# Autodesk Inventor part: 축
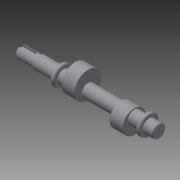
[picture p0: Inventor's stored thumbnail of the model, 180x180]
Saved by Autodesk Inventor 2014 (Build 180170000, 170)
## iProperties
Created: 2014-12
Part Number: 축
Material: 일반
Document SubType Name: Modeling
Designer: Owner
Density: 1 g/cm^3
Appearance: 기본값
Author: Owner
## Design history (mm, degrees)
sketch "스케치1"
  geometry: L1 (-90, 0)-(90, 0); L2 (-90, 0)-(-90, 7.5); L3 (-90, 7.5)-(-66, 7.5); L4 (-66, 7.5)-(-66, 8.5); L5 (-66, 8.5)-(-39, 8.5); L6 (-39, 8.5)-(-39, 13); L7 (-39, 13)-(-34, 13); L8 (-34, 13)-(-34, 8.5); L9 (-34, 8.5)-(72, 8.5); L10 (72, 8.5)-(72, 13); L11 (72, 13)-(77, 13); L12 (77, 13)-(77, 8.5); L13 (77, 8.5)-(90, 8.5); L14 (90, 8.5)-(90, 0); 2 further points
  constraints: 28 end point, 7 parallel, 4 perpendicular, 3 collinear, 3 horizontal alignment, 1 coincident, 1 horizontal, 1 midpoint
  dimensions: "d0" = 180 distance of L1.start L1.end; "d2" = 15 diameter of L3 L1; "d3" = 17 diameter of L5 L1; "d4" = 26 diameter of L7 L1; "d5" = 5 distance of L10.end L11.end; "d6" = 13 distance of L12.end L13.end; "d7" = 24 distance of L2.end L3.end; "d8" = 27 distance of L4.end L5.end
revolve "회전1" sketch "스케치1" stored, may be unused: angle "d9" = 90 deg
node "작업 평면1"
sketch "스케치2"
  geometry: L1 (-7.547, 0)-(5.5, 0); L2 (-12, -2.5)-(5.5, -2.5); L3 (5.5, 2.5)-(-12, 2.5); L4 (-12, 2.5)-(-12, -2.5); L5 (-12, -7.5)-(-12, 7.5) reference; A1 r 2.5 centre (5.5, 0) between (5.5, -2.5) and (5.5, 2.5); 4 further points
  constraints: 10 end point, 4 midpoint, 2 horizontal alignment, 2 point on circle, 2 tangent, 1 centre point, 1 horizontal, 1 parallel, 1 perpendicular, 1 vertical
  dimensions: "d10" = 20 dimension on A1 L5; "d11" = 5 distance of L3.end L2.start
extrude "돌출1" cut sketch "스케치2" distance "d12" = 3; taper "d13" = 0 deg
node "작업 평면3"
  node "작업 평면2"
sketch "스케치3"
  geometry: C1 r 17.5 at (0, 6); 1 further point
  constraints: 1 centre point, 1 vertical alignment
  dimensions: "d16" = 35 diameter of C1; "d17" = 6 distance of point (0, 0) C1.centre
extrude "돌출2" join sketch "스케치3" distance "d18" = 17; taper "d19" = 0 deg
node "작업 평면4"
sketch "스케치4"
  geometry: C1 r 15 at (0, -5); 1 further point
  constraints: 1 centre point, 1 vertical alignment
  dimensions: "d22" = 30 diameter of C1; "d23" = 5 distance of C1.centre point (0, 0)
extrude "돌출3" join sketch "스케치4" distance "d24" = 17; taper "d25" = 0 deg
chamfer "모따기1" distance "d26" = 1; stored, may be unused: second distance "d27" = 2, angle "d28" = 45 deg
node "솔리드1"
other parameters: "d15" = 70.5
